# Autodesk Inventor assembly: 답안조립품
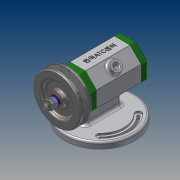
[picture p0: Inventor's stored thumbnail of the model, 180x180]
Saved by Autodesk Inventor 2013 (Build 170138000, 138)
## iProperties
Created: 2017-06
Part Number: 답안조립품
Document SubType Name: Assembly
Designer: Windows7
Author: Windows7
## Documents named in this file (13)
- C:\Users\Windows7\Desktop\470608V1025\답안조립품.iam
- C:\Users\Windows7\Desktop\470608V1025\본체.ipt
- C:\Users\Windows7\Desktop\470608V1025\베어링 15 x 32 x 9.ipt
- C:\Users\Windows7\Desktop\470608V1025\축.ipt
- C:\Users\Windows7\Desktop\470608V1025\키 3 x 3 x 12.ipt
- C:\Users\Windows7\Desktop\470608V1025\앞커버.ipt
- C:\Users\Windows7\Desktop\470608V1025\볼트 M4 x 12.ipt
- C:\Users\Windows7\Desktop\470608V1025\뒤커버.ipt
- C:\Users\Windows7\Desktop\470608V1025\오일 실 15 25 7.ipt
- C:\Users\Windows7\Desktop\470608V1025\V벨트풀리.ipt
- C:\Users\Windows7\Desktop\470608V1025\와셔 8x17.ipt
- C:\Users\Windows7\Desktop\470608V1025\스프링와셔 8.ipt
- C:\Users\Windows7\Desktop\470608V1025\너트 M 8.ipt
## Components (1 placed, 1 different names)
1. V벨트풀리:1
